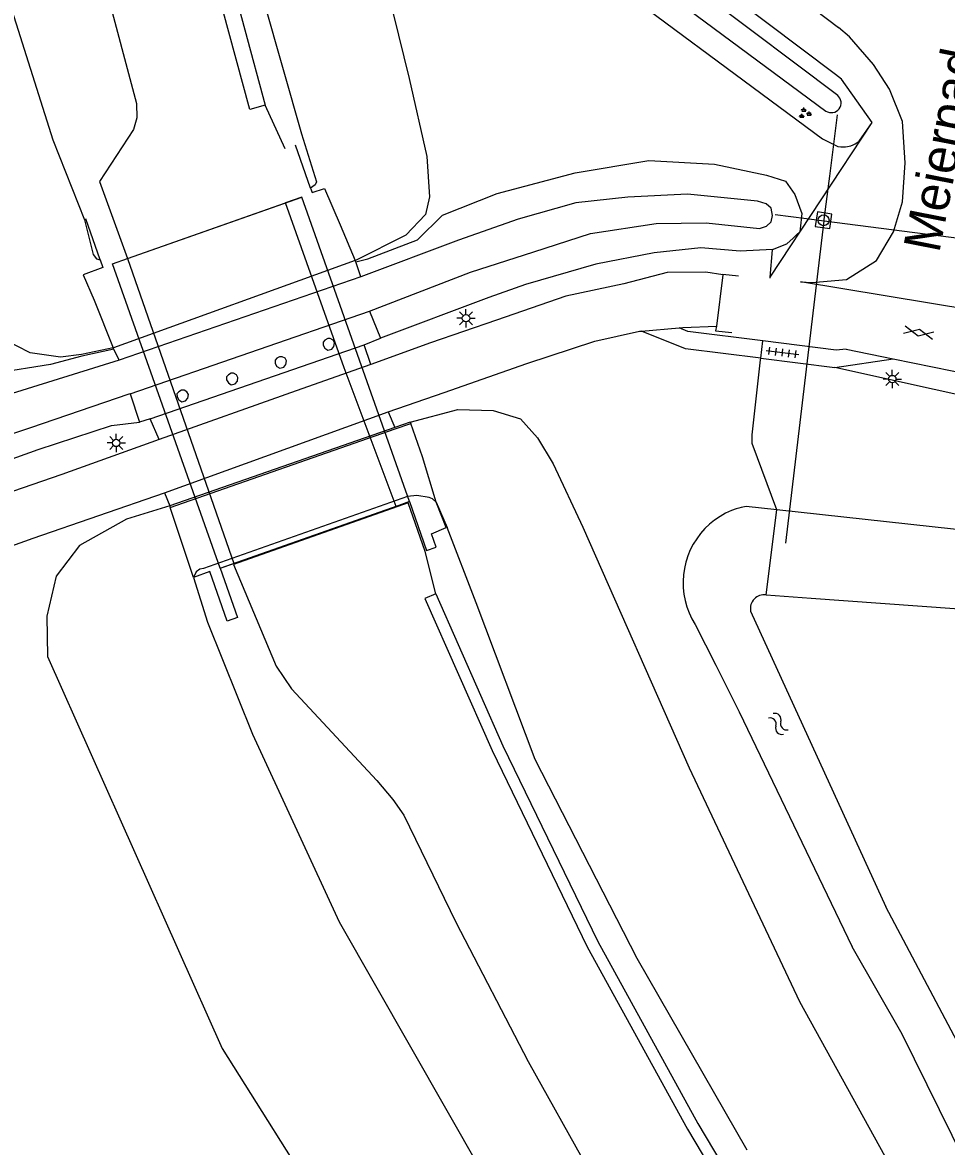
# Model space of a CAD drawing. Extents: x 135999 to 138000, y 396000 to 398501.
# Drawn here: x 137094.8 to 137157.7, y 396083.9 to 396160.4 of the extents above; entities that cross this region are included whole.
import ezdxf

# ---------------------------------------------------------------- set-up
doc = ezdxf.new("R2010")
doc.units = 0
for name, color, linetype in [('gg-afsc-draadraster', 7, 'Continuous'), ('gg-afsc-faunaraster', 7, 'Continuous'), ('gg-afsc-lijn draadraster', 7, 'Continuous'), ('gg-anno-openbare ruimte label', 7, 'Continuous'), ('gg-knt-BGT kruinlijn', 7, 'Continuous'), ('gg-knt-bronhoudergrens niveau 01', 7, 'Continuous'), ('gg-knt-verharding', 7, 'Continuous'), ('gg-kntw-bovenkant insteek waterloop', 7, 'Continuous'), ('gg-kntw-waterlijn', 7, 'Continuous'), ('gg-kwrk-duiker nz buis', 7, 'Continuous'), ('gt-grn-groengrens', 7, 'Continuous'), ('gt-grn-vlakafsluiter', 7, 'Continuous'), ('gt-grn-weggrens', 7, 'Continuous'), ('gt-symb-gesloten verharding', 7, 'Continuous'), ('gt-symb-groenvak', 7, 'Continuous'), ('gt-symb-lichtmast', 7, 'Continuous'), ('gt-symb-rioolschacht', 7, 'Continuous'), ('gt-symb-tegel verharding', 7, 'Continuous'), ('gt-symb-watersymbool', 7, 'Continuous'), ('gx-grn-maaiveld', 7, 'Continuous')]:
    doc.layers.add(name, color=color, linetype=linetype)

# ---------------------------------------------------------------- blocks, each defined once
blk = doc.blocks.new('gt0-GRVAK')
at = {"layer": 'gt-symb-groenvak'}
for p, q in [((-0.11, 0.189), (-0.228, 0.24)), ((-0.182, 0.153), (0.088, 0.153)), ((-0.091, 0.211), (-0.156, 0.322)), ((-0.047, 0.214), (-0.047, 0.393)), ((-0.004, 0.211), (0.061, 0.322)), ((0.015, 0.189), (0.133, 0.24)), ((0.262, -0.052), (0.197, 0.059)), ((0.305, -0.049), (0.305, 0.13)), ((0.349, -0.052), (0.414, 0.059)), ((-0.245, -0.228), (-0.363, -0.177)), ((-0.318, -0.264), (-0.047, -0.264)), ((-0.226, -0.206), (-0.291, -0.095)), ((-0.183, -0.203), (-0.183, -0.024)), ((-0.139, -0.206), (-0.074, -0.095)), ((-0.12, -0.228), (-0.002, -0.177)), ((0.243, -0.074), (0.125, -0.023)), ((0.17, -0.11), (0.441, -0.11)), ((0.368, -0.074), (0.486, -0.023))]:
    blk.add_line(p, q, dxfattribs=at)
blk = doc.blocks.new('gt0-LMAST')
at = {"layer": 'gt-symb-lichtmast'}
for p, q in [((-0.182, 0.173), (-0.447, 0.438)), ((-0.005, 0.246), (-0.005, 0.621)), ((0.172, 0.173), (0.437, 0.438)), ((-0.255, -0.004), (-0.63, -0.004)), ((-0.182, -0.181), (-0.447, -0.446)), ((-0.005, -0.254), (-0.005, -0.629)), ((0.437, -0.446), (0.172, -0.181)), ((0.245, -0.004), (0.62, -0.004))]:
    blk.add_line(p, q, dxfattribs=at)
blk.add_circle((-0.005, -0.004), 0.25, dxfattribs=at)
blk = doc.blocks.new('gt0-GESVH1')
at = {"layer": 'gt-symb-gesloten verharding'}
for p, q in [((-0.992, -0.261), (0.008, 0.239)), ((0.008, -0.261), (-0.992, 0.239)), ((0.008, 0.239), (1.008, -0.261)), ((1.008, 0.239), (0.008, -0.261))]:
    blk.add_line(p, q, dxfattribs=at)
blk = doc.blocks.new('gt0-RS')
at = {"layer": 'gt-symb-rioolschacht'}
blk.add_lwpolyline([(-0.5, -0.5), (0.5, -0.5), (0.5, 0.5), (-0.5, 0.5)], close=True, dxfattribs=at)
blk.add_circle((0, 0), 0.375, dxfattribs=at)
blk = doc.blocks.new('gt0-TEG1')
at = {"layer": 'gt-symb-tegel verharding'}
for p, q in [((-1.125, 0), (1.125, 0)), ((-0.9, -0.25), (-0.9, 0.25)), ((-0.45, -0.25), (-0.45, 0.25)), ((0, -0.25), (0, 0.25)), ((0.45, -0.25), (0.45, 0.25)), ((0.9, -0.25), (0.9, 0.25))]:
    blk.add_line(p, q, dxfattribs=at)
blk = doc.blocks.new('gt0-WA')
at = {"layer": 'gt-symb-watersymbool'}
for centre, start, end in [((-0.323, 0.022), 28.07249, 151.92751), ((0.427, 0.422), 208.07248, 331.92751), ((-0.323, -0.428), 28.07249, 151.92751), ((0.427, -0.028), 208.07248, 331.92751)]:
    blk.add_arc(centre, 0.425, start, end, dxfattribs=at)

msp = doc.modelspace()

# ---------------------------------------------------------------- linework, layer by layer
at = {"layer": 'gg-afsc-draadraster'}
msp.add_line((137145.056, 396137.435), (137145.069, 396137.541), dxfattribs=at)
msp.add_lwpolyline([(137146.152, 396127.219), (137144.485, 396131.739), (137144.483, 396132.313), (137145.056, 396137.435)], dxfattribs=at)
at = {"layer": 'gg-afsc-faunaraster'}
for p, q in [((137152.649, 396153.597), (137150.573, 396156.548)), ((137145.705, 396143.062), (137152.649, 396153.597)), ((137145.696, 396142.979), (137145.705, 396143.062)), ((137145.069, 396137.541), (137145.21, 396138.711))]:
    msp.add_line(p, q, dxfattribs=at)
at = {"layer": 'gg-afsc-lijn draadraster'}
msp.add_line((137145.056, 396137.435), (137145.069, 396137.541), dxfattribs=at)
msp.add_lwpolyline([(137146.152, 396127.219), (137144.485, 396131.739), (137144.483, 396132.313), (137145.056, 396137.435)], dxfattribs=at)
at = {"layer": 'gg-knt-BGT kruinlijn'}
for p, q in [((137093, 396164.565), (137096.827, 396152.402)), ((137111.224, 396161.737), (137113.772, 396152.811)), ((137113.772, 396152.811), (137114.793, 396149.55)), ((137096.827, 396152.402), (137098.983, 396146.959)), ((137114.4, 396149.124), (137113.373, 396152.041)), ((137114.793, 396149.55), (137114.71, 396149.337)), ((137114.71, 396149.337), (137114.4, 396149.124)), ((137101.929, 396144.332), (137113.807, 396148.512)), ((137098.983, 396146.959), (137099.574, 396144.592)), ((137100.063, 396144.24), (137099.082, 396147.029)), ((137099.574, 396144.592), (137099.819, 396144.31)), ((137099.819, 396144.31), (137100.063, 396144.24)), ((137120.991, 396128.13), (137107.092, 396123.224)), ((137121.624, 396128.182), (137120.991, 396128.13)), ((137122.485, 396128.061), (137121.624, 396128.182)), ((137122.703, 396127.964), (137122.485, 396128.061)), ((137122.947, 396127.736), (137122.703, 396127.964)), ((137122.947, 396127.736), (137123.694, 396126.018)), ((137125.672, 396120.875), (137123.694, 396126.018)), ((137106.594, 396122.997), (137106.411, 396122.604)), ((137106.86, 396123.17), (137106.594, 396122.997)), ((137107.092, 396123.224), (137106.86, 396123.17)), ((137106.411, 396122.604), (137107.378, 396119.572)), ((137129.698, 396110.214), (137125.672, 396120.875)), ((137107.378, 396119.572), (137110.443, 396111.936)), ((137110.443, 396111.936), (137116.34, 396099.163)), ((137136.653, 396096.652), (137129.698, 396110.214)), ((137116.34, 396099.163), (137127.487, 396079.652)), ((137144.131, 396083.605), (137136.653, 396096.652))]:
    msp.add_line(p, q, dxfattribs=at)
at = {"layer": 'gg-knt-bronhoudergrens niveau 01'}
for p, q in [((137101.929, 396144.332), (137112.697, 396148.121)), ((137113.807, 396148.512), (137112.697, 396148.121)), ((137121.135, 396127.77), (137113.807, 396148.512)), ((137100.905, 396143.972), (137101.929, 396144.332)), ((137101.929, 396144.332), (137109.171, 396123.56)), ((137108.231, 396123.229), (137100.905, 396143.972)), ((137109.171, 396123.56), (137120.218, 396127.447)), ((137121.135, 396127.77), (137120.218, 396127.447)), ((137108.231, 396123.229), (137109.171, 396123.56))]:
    msp.add_line(p, q, dxfattribs=at)
msp.add_lwpolyline([(137120.218, 396127.447), (137116.68, 396136.886), (137112.697, 396148.121)], dxfattribs=at)
at = {"layer": 'gg-knt-verharding'}
for p, q in [((137150.203, 396138.09), (137145.21, 396138.711)), ((137150.882, 396138.156), (137150.203, 396138.09)), ((137150.882, 396138.156), (137154.081, 396137.497)), ((137145.069, 396137.541), (137150.111, 396136.915)), ((137150.111, 396136.915), (137154.081, 396137.497)), ((137154.081, 396137.497), (137160.414, 396136.192))]:
    msp.add_line(p, q, dxfattribs=at)
for points in [[(137130.569, 396174.664), (137146.262, 396163.187), (137150.355, 396160.063)], [(137147.773, 396142.729), (137148.545, 396142.691), (137150.907, 396142.892), (137152.961, 396144.197), (137154.107, 396146.136), (137154.713, 396148.195), (137154.901, 396150.848), (137154.716, 396153.652), (137153.847, 396155.87), (137152.735, 396157.547), (137151.12, 396159.42), (137150.355, 396160.063)], [(137145.21, 396138.711), (137140.103, 396139.347), (137139.5, 396139.601)], [(137145.069, 396137.541), (137139.947, 396138.176), (137136.93, 396139.382)]]:
    msp.add_lwpolyline(points, dxfattribs=at)
at = {"layer": 'gg-kntw-bovenkant insteek waterloop'}
for p, q in [((137150.163, 396156.857), (137131.061, 396171.237)), ((137150.573, 396156.548), (137150.163, 396156.857)), ((137151.76, 396152.315), (137152.649, 396153.597)), ((137145.427, 396121.416), (137148.495, 396121.193)), ((137144.376, 396120.313), (137153.596, 396100.171)), ((137160.201, 396087.677), (137153.596, 396100.171))]:
    msp.add_line(p, q, dxfattribs=at)
for points in [[(137386.348, 396073.068), (137346.791, 396088.162), (137287.011, 396106.121), (137247.2, 396114.57), (137201.971, 396121.101), (137146.152, 396127.219)], [(137148.495, 396121.193), (137163.296, 396120.118), (137192.816, 396117.687)], [(137228.649, 396003.575), (137220.719, 396008.229), (137214.987, 396012.081), (137209.31, 396016.468), (137202.71, 396022.81), (137193.899, 396032.607), (137182.394, 396047.186), (137169.5, 396065.852), (137158.945, 396082.906), (137154.696, 396091.499), (137151.284, 396097.455)]]:
    msp.add_lwpolyline(points, dxfattribs=at)
for centre, radius, start, end in [((137150.666, 396153.634), 1.709, 272.06536, 288.15872), ((137150.668, 396153.656), 1.729, 287.8919, 309.17147), ((137145.297, 396120.488), 0.937, 82.02391, 190.74192)]:
    msp.add_arc(centre, radius, start, end, dxfattribs=at)
at = {"layer": 'gg-kntw-waterlijn'}
msp.add_line((137150.305, 396155.436), (137130.395, 396170.424), dxfattribs=at)
msp.add_lwpolyline([(137129.568, 396169.155), (137138.926, 396162.215), (137149.503, 396154.371)], dxfattribs=at)
msp.add_arc((137149.869, 396154.93), 0.668, 236.73393, 49.3028, dxfattribs=at)
at = {"layer": 'gg-kwrk-duiker nz buis'}
for p, q in [((137149.768, 396149.945), (137150.295, 396154.11)), ((137149.723, 396149.589), (137149.768, 396149.945)), ((137146.047, 396147.331), (137148.179, 396147.056)), ((137148.177, 396136.788), (137149.384, 396146.9)), ((137148.179, 396147.056), (137149.384, 396146.9)), ((137149.384, 396146.9), (137162.254, 396145.24)), ((137146.764, 396124.948), (137148.177, 396136.788))]:
    msp.add_line(p, q, dxfattribs=at)
msp.add_lwpolyline([(137149.384, 396146.9), (137149.394, 396146.984), (137149.723, 396149.589)], dxfattribs=at)
at = {"layer": 'gt-grn-groengrens'}
msp.add_lwpolyline([(137393.292, 396077.029), (137381.074, 396082.146), (137364.629, 396088.304), (137349.968, 396093.653), (137328.049, 396100.593), (137325.581, 396101.36), (137308.104, 396106.595), (137298.245, 396109.46), (137289.192, 396111.783), (137275.222, 396115.233), (137266.321, 396117.187), (137257.904, 396118.985), (137251.254, 396120.084), (137231.893, 396123.182), (137223.368, 396124.4), (137207.73, 396126.262), (137186.92, 396128.76), (137150.111, 396136.915)], dxfattribs=at)
at = {"layer": 'gt-grn-vlakafsluiter'}
msp.add_line((137145.427, 396121.416), (137146.152, 396127.219), dxfattribs=at)
at = {"layer": 'gt-grn-weggrens'}
msp.add_line((137161.155, 396140.529), (137147.773, 396142.729), dxfattribs=at)
at = {"layer": 'gx-grn-maaiveld'}
for p, q in [((137112.654, 396151.788), (137111.31, 396154.773)), ((137147.861, 396147.387), (137147.749, 396146.349)), ((137147.495, 396145.933), (137147.263, 396145.716)), ((137145.868, 396144.91), (137145.87, 396144.938)), ((137117.476, 396144.107), (137117.437, 396144.197)), ((137145.705, 396143.062), (137145.868, 396144.91)), ((137117.828, 396143.07), (137117.476, 396144.107)), ((137117.828, 396143.07), (137101.365, 396137.404)), ((137142.472, 396143.204), (137142.04, 396139.709)), ((137102.105, 396135.115), (137118.408, 396140.75)), ((137118.408, 396140.75), (137119.165, 396138.911)), ((137136.93, 396139.382), (137139.5, 396139.601)), ((137118.038, 396138.45), (137119.165, 396138.911)), ((137100.985, 396138.15), (137100.948, 396138.242)), ((137101.365, 396137.404), (137100.985, 396138.15)), ((137103.468, 396133.409), (137118.038, 396138.45)), ((137118.504, 396137.1), (137118.038, 396138.45)), ((137102.105, 396135.115), (137102.734, 396133.191)), ((137104.453, 396128.374), (137119.679, 396133.882)), ((137119.679, 396133.882), (137120.125, 396132.812)), ((137103.468, 396133.409), (137102.734, 396133.191)), ((137104.075, 396132), (137103.468, 396133.409)), ((137120.125, 396132.812), (137104.807, 396127.473)), ((137121.19, 396133.184), (137120.125, 396132.812)), ((137121.19, 396133.184), (137121.223, 396133.09)), ((137104.453, 396128.374), (137104.807, 396127.473)), ((137104.807, 396127.473), (137104.838, 396127.379)), ((137106.411, 396122.604), (137104.838, 396127.379)), ((137108.231, 396123.229), (137121.135, 396127.77)), ((137146.152, 396127.219), (137144.061, 396127.448))]:
    msp.add_line(p, q, dxfattribs=at)
for points in [[(137111.31, 396154.773), (137110.248, 396154.486), (137107.466, 396164.773), (137105.204, 396173.779), (137102.557, 396186.821), (137100.774, 396196.903), (137099.167, 396209.421), (137098.137, 396219.857), (137097.45, 396230.691), (137097.067, 396243.142), (137097.214, 396253.776), (137097.802, 396266.448), (137098.479, 396275.725), (137099.623, 396285.935), (137101.085, 396295.747), (137102.21, 396302.757), (137103.668, 396310.189), (137105.241, 396317.642), (137107.019, 396324.975), (137109.155, 396333.02), (137111.23, 396340.022)], [(137105.551, 396313.783), (137104.746, 396309.97), (137103.293, 396302.564), (137102.172, 396295.579), (137100.714, 396285.793), (137099.575, 396275.624), (137098.9, 396266.383), (137098.314, 396253.743), (137098.167, 396243.151), (137098.549, 396230.743), (137099.234, 396219.946), (137100.26, 396209.545), (137101.862, 396197.069), (137103.638, 396187.026), (137106.277, 396174.023), (137108.53, 396165.051), (137111.31, 396154.773)], [(137114.596, 396215.194), (137117.057, 396199.262), (137119.969, 396184.983), (137120.76, 396181.136), (137121.45, 396178.397), (137122.733, 396175.636), (137124.103, 396173.251), (137126.141, 396170.606), (137128.814, 396167.982), (137132.033, 396165.267), (137149.262, 396152.477), (137150.322, 396151.958)], [(137109.982, 396213.604), (137113.95, 396190.543), (137115.818, 396179.417), (137117.801, 396170.064), (137121.115, 396156.589), (137122.318, 396151.27), (137122.488, 396148.538), (137122.227, 396147.326), (137120.877, 396145.915), (137117.448, 396144.201), (137117.437, 396144.197)], [(137092.86, 396200.87), (137094.967, 396186.91), (137097.836, 396173.47), (137100.417, 396162.827), (137102.541, 396154.887), (137102.56, 396153.898), (137102.323, 396153.116), (137100.017, 396149.562), (137101.929, 396144.332)], [(137100.985, 396138.15), (137098.816, 396137.685), (137096.667, 396137.113), (137092.958, 396136.515), (137085.594, 396135.477), (137083.118, 396135.48), (137079.866, 396136.101), (137075.263, 396137.509), (137070.656, 396138.941), (137065.89, 396139.411), (137050.828, 396141.515), (137041.308, 396143.808), (137021.396, 396150.362), (137009.735, 396153.947), (137001.52, 396157.307), (136992.445, 396161.933), (136990.59, 396162.426), (136987.796, 396162.155), (136986.192, 396161.589)], [(137101.365, 396137.404), (137093.698, 396135.031), (137086.311, 396133.626), (137083.959, 396133.514), (137081.67, 396133.921), (137074.443, 396135.392), (137057.33, 396138.182), (137043.72, 396140.499), (137030.936, 396144.752), (137012.505, 396150.204), (137001.396, 396154.626), (136994.302, 396157.911), (136990.674, 396159.575), (136987.531, 396160.113), (136986.781, 396160.033)], [(136983.972, 396157.977), (136984.347, 396156.549), (136986.155, 396154.261), (137000.379, 396142.528), (137010.255, 396134.348), (137017.889, 396127.274), (137026.111, 396120.041), (137029.572, 396117.467), (137031.791, 396116.176), (137036.972, 396114.256), (137040.766, 396112.941), (137044.39, 396112.951), (137047.656, 396113.644), (137052.766, 396115.359), (137075.182, 396123.931), (137095.838, 396131.318), (137100.825, 396132.953), (137102.734, 396133.191)], [(137102.105, 396135.115), (137102.021, 396135.086), (137095.322, 396132.797), (137069.593, 396124.204), (137049.049, 396116.536), (137045.807, 396115.762), (137041.666, 396115.595), (137038.675, 396115.809), (137035.074, 396116.545), (137031.409, 396117.71), (137028.424, 396119.294), (137025.548, 396121.399), (137016.318, 396129.845), (137009.2, 396136.397), (136994.313, 396148.401), (136990.513, 396152.123), (136985.383, 396157.45)], [(137150.322, 396151.958), (137150.524, 396151.93), (137150.525, 396151.93), (137150.724, 396151.926), (137150.728, 396151.926)], [(137117.476, 396144.107), (137118.293, 396144.312), (137121.69, 396145.6), (137123.384, 396147.284), (137127.1, 396148.761), (137132.419, 396150.154), (137137.438, 396150.993), (137141.919, 396150.756), (137145.449, 396149.996), (137146.755, 396149.599), (137147.388, 396148.688), (137147.861, 396147.387)], [(137114.4, 396149.124), (137114.509, 396148.813), (137115.339, 396149.105), (137116.4, 396146.618), (137117.437, 396144.197)], [(137118.408, 396140.75), (137125.293, 396143.396), (137129.611, 396144.78), (137133.459, 396146.033), (137137.94, 396146.708), (137141.349, 396146.759), (137144.983, 396146.371), (137145.452, 396146.53), (137145.78, 396146.824), (137145.874, 396147.258), (137145.763, 396147.748), (137145.441, 396148.044), (137144.834, 396148.24), (137140.077, 396148.708), (137136, 396148.513), (137132.465, 396148.114), (137128.544, 396147.017), (137124.483, 396145.582), (137117.828, 396143.07)], [(137145.87, 396144.938), (137146.842, 396145.321), (137147.263, 396145.716)], [(137147.749, 396146.349), (137147.727, 396146.151), (137147.495, 396145.933)], [(137145.87, 396144.938), (137143.668, 396144.823), (137140.985, 396145.047), (137137.805, 396144.724), (137133.822, 396143.939), (137129.029, 396142.558), (137126.531, 396141.664), (137119.165, 396138.911)], [(137100.063, 396144.24), (137100.251, 396143.707), (137098.901, 396143.223), (137099.643, 396141.482), (137100.948, 396138.242)], [(137117.437, 396144.197), (137100.959, 396138.244), (137100.948, 396138.242)], [(137142.472, 396143.204), (137141.315, 396143.397), (137138.695, 396143.384), (137135.734, 396142.612), (137131.787, 396141.754), (137127.063, 396140.12), (137122.559, 396138.58), (137118.504, 396137.1)], [(137142.472, 396143.204), (137142.478, 396143.266), (137143.541, 396143.155)], [(137139.5, 396139.601), (137139.763, 396139.623), (137142.04, 396139.709)], [(137142.04, 396139.709), (137141.991, 396139.403), (137143.086, 396139.28)], [(137100.948, 396138.242), (137098.794, 396137.78), (137097.35, 396137.608), (137095.292, 396137.899), (137093.526, 396138.82)], [(137115.374, 396138.77), (137115.249, 396138.631), (137115.251, 396138.416), (137115.374, 396138.216), (137115.574, 396138.093), (137115.836, 396138.154), (137115.99, 396138.339), (137116.021, 396138.586), (137115.928, 396138.77), (137115.728, 396138.878), (137115.559, 396138.876), (137115.374, 396138.77)], [(137119.679, 396133.882), (137123.487, 396135.192), (137129.137, 396137.178), (137133.768, 396138.7), (137136.813, 396139.372), (137136.93, 396139.382)], [(137112.102, 396137.533), (137111.976, 396137.393), (137111.979, 396137.179), (137112.102, 396136.979), (137112.302, 396136.856), (137112.564, 396136.917), (137112.718, 396137.102), (137112.749, 396137.349), (137112.656, 396137.533), (137112.456, 396137.641), (137112.287, 396137.639), (137112.102, 396137.533)], [(137118.504, 396137.1), (137113.42, 396135.312), (137104.075, 396132)], [(137108.792, 396136.409), (137108.657, 396136.271), (137108.669, 396136.055), (137108.792, 396135.855), (137108.992, 396135.732), (137109.254, 396135.793), (137109.408, 396135.978), (137109.439, 396136.225), (137109.346, 396136.409), (137109.146, 396136.517), (137108.977, 396136.515), (137108.792, 396136.409)], [(137105.42, 396135.254), (137105.281, 396135.116), (137105.297, 396134.9), (137105.42, 396134.7), (137105.62, 396134.577), (137105.882, 396134.638), (137106.036, 396134.823), (137106.067, 396135.07), (137105.974, 396135.254), (137105.774, 396135.362), (137105.605, 396135.36), (137105.42, 396135.254)], [(137121.19, 396133.184), (137124.416, 396134.051), (137126.841, 396133.983), (137128.693, 396133.412), (137129.845, 396132.115), (137130.917, 396130.34), (137132.94, 396126.041), (137140.191, 396109.648), (137147.7, 396093.736), (137156.425, 396077.923), (137171.506, 396054.527), (137183.213, 396038.52), (137196.797, 396022.177), (137209.108, 396009.699), (137218.998, 396000.708), (137219.893, 396000)], [(137104.838, 396127.379), (137120.157, 396132.718), (137121.223, 396133.09)], [(137122.947, 396127.736), (137122.017, 396130.811), (137121.223, 396133.09)], [(137104.075, 396132), (137097.443, 396129.623), (137084.633, 396125.205), (137071.63, 396120.462), (137062.34, 396117.233), (137056.859, 396115.207), (137050.899, 396112.834), (137043.514, 396109.444), (137037.849, 396106.418)], [(137040.048, 396103.526), (137045.575, 396106.475), (137051.56, 396109.111), (137057.772, 396111.707), (137064.784, 396114.239), (137080.449, 396119.889), (137095.496, 396125.281), (137104.453, 396128.374)], [(137104.807, 396127.473), (137101.86, 396126.578), (137098.66, 396124.789), (137097.065, 396122.693), (137096.416, 396119.98), (137096.467, 396117.223), (137108.378, 396090.53), (137122.501, 396068.092), (137129.609, 396057.328), (137135.645, 396049.332), (137142.799, 396040.131), (137147.222, 396034.544), (137159.603, 396020.573), (137167.826, 396012.367), (137177.963, 396002.547), (137180.807, 396000)], [(137122.917, 396121.498), (137122.195, 396124.383), (137121.04, 396127.684), (137109.132, 396123.493), (137112.056, 396116.574), (137113.089, 396115.016), (137118.912, 396108.787), (137120.008, 396107.491), (137120.747, 396106.41), (137124.285, 396099.123), (137129.209, 396089.644), (137133.325, 396082.276), (137137.505, 396075.055), (137144.918, 396063.142), (137150.863, 396054.636), (137157.103, 396046.158), (137164.28, 396037.054), (137170.618, 396029.503), (137176.794, 396022.635), (137184.078, 396015.115), (137190.911, 396008.315), (137199.846, 396000)], [(137121.135, 396127.77), (137122.303, 396124.448), (137122.955, 396124.677)], [(137122.955, 396124.677), (137122.641, 396125.568), (137123.636, 396126), (137122.947, 396127.736)], [(137144.061, 396127.448), (137143.727, 396127.372), (137143.561, 396127.326), (137143.398, 396127.275), (137143.076, 396127.156)], [(137143.076, 396127.156), (137142.674, 396126.973), (137142.289, 396126.758), (137141.923, 396126.51), (137141.579, 396126.234), (137141.259, 396125.93), (137140.966, 396125.6), (137140.701, 396125.246), (137140.467, 396124.872), (137140.265, 396124.48), (137140.095, 396124.072), (137140.074, 396124.011), (137140.023, 396123.861), (137139.961, 396123.652), (137139.862, 396123.222), (137139.799, 396122.785), (137139.773, 396122.344), (137139.783, 396121.903), (137139.831, 396121.464), (137139.914, 396121.031), (137140.034, 396120.606), (137140.189, 396120.192), (137140.377, 396119.793), (137140.598, 396119.411)], [(137108.722, 396119.636), (137107.537, 396123.003), (137106.411, 396122.604)], [(137108.231, 396123.229), (137109.41, 396119.878), (137108.722, 396119.636)], [(137122.917, 396121.498), (137122.186, 396121.174), (137126.777, 396110.812), (137133.247, 396097.453), (137140.084, 396085.023), (137146.278, 396074.612), (137155.641, 396060.647), (137164.459, 396048.618), (137173.292, 396037.784), (137180.261, 396029.783), (137188.568, 396021.005), (137196.459, 396013.132), (137205.069, 396005.223), (137211.131, 396000)], [(137122.917, 396121.498), (137127.503, 396111.149), (137133.958, 396097.82), (137140.778, 396085.42), (137146.954, 396075.04), (137156.296, 396061.106), (137165.092, 396049.108), (137173.904, 396038.3), (137180.853, 396030.321), (137189.141, 396021.563), (137197.012, 396013.71), (137205.601, 396005.821), (137212.356, 396000)], [(137140.598, 396119.411), (137141.997, 396116.625), (137143.588, 396113.455), (137151.284, 396097.455)]]:
    msp.add_lwpolyline(points, dxfattribs=at)

# ---------------------------------------------------------------- block references
at = {"layer": 'gt-symb-gesloten verharding', "rotation": 168.3415983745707}
msp.add_blockref('gt0-GESVH1', (137155.836, 396139.265), dxfattribs=at)
at = {"layer": 'gt-symb-groenvak'}
msp.add_blockref('gt0-GRVAK', (137148.052, 396154.209), dxfattribs=at)
at = {"layer": 'gt-symb-lichtmast'}
for p in [(137124.988, 396140.261), (137154.032, 396136.122), (137101.157, 396131.769)]:
    msp.add_blockref('gt0-LMAST', p, dxfattribs=at)
at = {"layer": 'gt-symb-rioolschacht', "rotation": 81.37577126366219}
msp.add_blockref('gt0-RS', (137149.344, 396146.933), dxfattribs=at)
at = {"layer": 'gt-symb-tegel verharding', "rotation": -7.068140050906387}
msp.add_blockref('gt0-TEG1', (137146.548, 396137.922), dxfattribs=at)
at = {"layer": 'gt-symb-watersymbool', "rotation": -47.148091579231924}
msp.add_blockref('gt0-WA', (137146.23, 396112.672), dxfattribs=at)

# ---------------------------------------------------------------- texts
at = {"layer": 'gg-anno-openbare ruimte label'}
msp.add_text('Meierpad', height=2.5, rotation=78.9, dxfattribs=at).set_placement((137157.22, 396144.651))

doc.saveas('drawing.dxf')
